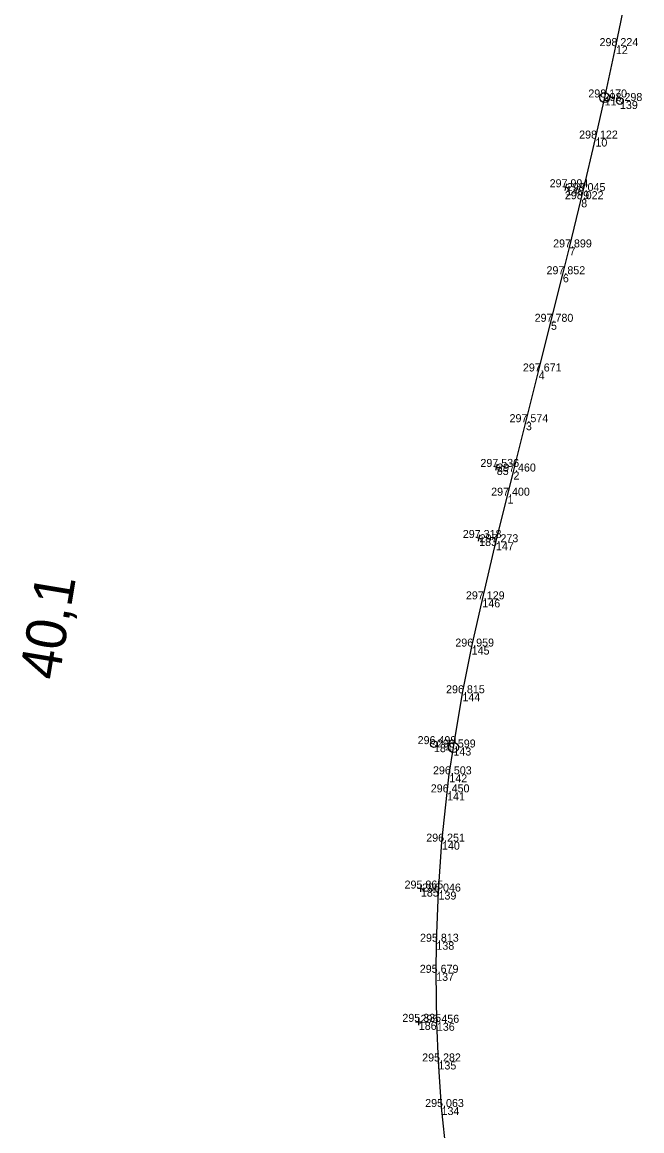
# Model space of a CAD drawing. Extents: x -684938 to -684389, y -1007777 to -1006471.
# Drawn here: x -684578.3 to -684485.4, y -1007291.1 to -1007124.9 of the extents above; entities that cross this region are included whole.
import ezdxf

# ---------------------------------------------------------------- set-up
doc = ezdxf.new("R2010")
doc.units = 0
for name, color, linetype in [('Vrstva 1', 7, 'Continuous'), ('Vrstva 60', 7, 'Continuous'), ('Vrstva 61', 7, 'Continuous'), ('Vrstva 7', 7, 'Continuous')]:
    doc.layers.add(name, color=color, linetype=linetype)

msp = doc.modelspace()

# ---------------------------------------------------------------- linework, layer by layer
at = {"layer": 'Vrstva 1'}
msp.add_lwpolyline([(-684514.7, -1007294.72), (-684515.43, -1007287.58), (-684515.89, -1007280.75), (-684516.13, -1007274.95), (-684516.23, -1007267.46), (-684516.2, -1007262.8), (-684515.88, -1007255.28), (-684515.36, -1007247.8), (-684514.59, -1007240.41), (-684514.26, -1007237.7), (-684513.65, -1007233.68), (-684512.29, -1007225.55), (-684510.91, -1007218.55), (-684509.31, -1007211.47), (-684507.27, -1007202.91), (-684505.54, -1007195.93), (-684504.64, -1007192.31), (-684502.78, -1007184.91), (-684500.87, -1007177.31), (-684499.02, -1007169.86), (-684497.24, -1007162.73), (-684496.25, -1007158.71), (-684494.49, -1007151.48), (-684494.2, -1007150.27), (-684492.36, -1007142.39), (-684490.97, -1007136.23), (-684489.29, -1007128.53), (-684487.68, -1007120.78)], dxfattribs=at)
at = {"layer": 'Vrstva 60'}
for p, q in [((-684489.29, -1007128.53), (-684489.29, -1007128.53)), ((-684490.97, -1007136.23), (-684490.97, -1007136.23)), ((-684488.68, -1007136.76), (-684488.68, -1007136.76)), ((-684492.36, -1007142.39), (-684492.36, -1007142.39)), ((-684496.77, -1007149.69), (-684496.77, -1007149.69)), ((-684494.2, -1007150.27), (-684494.2, -1007150.27)), ((-684494.49, -1007151.48), (-684494.49, -1007151.48)), ((-684496.25, -1007158.71), (-684496.25, -1007158.71)), ((-684497.24, -1007162.73), (-684497.24, -1007162.73)), ((-684499.02, -1007169.86), (-684499.02, -1007169.86)), ((-684500.87, -1007177.31), (-684500.87, -1007177.31)), ((-684502.78, -1007184.91), (-684502.78, -1007184.91)), ((-684507.15, -1007191.62), (-684507.15, -1007191.62)), ((-684504.64, -1007192.31), (-684504.64, -1007192.31)), ((-684505.54, -1007195.93), (-684505.54, -1007195.93)), ((-684509.79, -1007202.27), (-684509.79, -1007202.27)), ((-684507.27, -1007202.91), (-684507.27, -1007202.91)), ((-684509.31, -1007211.47), (-684509.31, -1007211.47)), ((-684510.91, -1007218.55), (-684510.91, -1007218.55)), ((-684512.29, -1007225.55), (-684512.29, -1007225.55)), ((-684516.56, -1007233.18), (-684516.56, -1007233.18)), ((-684513.65, -1007233.68), (-684513.65, -1007233.68)), ((-684514.26, -1007237.7), (-684514.26, -1007237.7)), ((-684514.59, -1007240.41), (-684514.59, -1007240.41)), ((-684515.36, -1007247.8), (-684515.36, -1007247.8)), ((-684518.52, -1007254.83), (-684518.52, -1007254.83)), ((-684515.88, -1007255.28), (-684515.88, -1007255.28)), ((-684516.2, -1007262.8), (-684516.2, -1007262.8)), ((-684516.23, -1007267.46), (-684516.23, -1007267.46)), ((-684518.84, -1007274.81), (-684518.84, -1007274.81)), ((-684516.13, -1007274.95), (-684516.13, -1007274.95)), ((-684515.89, -1007280.75), (-684515.89, -1007280.75)), ((-684515.43, -1007287.58), (-684515.43, -1007287.58))]:
    msp.add_line(p, q, dxfattribs=at)
at = {"layer": 'Vrstva 7'}
for p, q in [((-684488.69, -1007136.81), (-684488.67, -1007136.71)), ((-684496.88, -1007150.18), (-684496.65, -1007149.2)), ((-684497.25, -1007149.57), (-684496.28, -1007149.8)), ((-684507.64, -1007191.5), (-684506.67, -1007191.75)), ((-684507.27, -1007192.11), (-684507.03, -1007191.14)), ((-684510.27, -1007202.15), (-684509.3, -1007202.39)), ((-684509.91, -1007202.75), (-684509.67, -1007201.78)), ((-684516.56, -1007233.23), (-684516.55, -1007233.13)), ((-684519.02, -1007254.79), (-684518.02, -1007254.86)), ((-684518.55, -1007255.32), (-684518.48, -1007254.33)), ((-684519.34, -1007274.82), (-684518.34, -1007274.81)), ((-684518.83, -1007275.31), (-684518.85, -1007274.31))]:
    msp.add_line(p, q, dxfattribs=at)
for centre, radius in [((-684490.97, -1007136.24), 0.75), ((-684488.68, -1007136.76), 0.5), ((-684516.56, -1007233.18), 0.5), ((-684513.65, -1007233.67), 0.75)]:
    msp.add_circle(centre, radius, dxfattribs=at)

# ---------------------------------------------------------------- texts
at = {"layer": 'Vrstva 60'}
for s, p in [('12', (-684489.29, -1007129.72)), ('11', (-684490.97, -1007137.43)), ('139', (-684488.68, -1007137.96)), ('10', (-684492.36, -1007143.59)), ('140', (-684496.77, -1007150.89)), ('9', (-684494.2, -1007151.47)), ('8', (-684494.49, -1007152.69)), ('7', (-684496.25, -1007159.91)), ('6', (-684497.24, -1007163.93)), ('5', (-684499.02, -1007171.06)), ('4', (-684500.87, -1007178.51)), ('3', (-684502.78, -1007186.11)), ('85', (-684507.15, -1007192.82)), ('2', (-684504.64, -1007193.51)), ('1', (-684505.54, -1007197.13)), ('183', (-684509.79, -1007203.47)), ('147', (-684507.27, -1007204.11)), ('146', (-684509.31, -1007212.67)), ('145', (-684510.91, -1007219.75)), ('144', (-684512.29, -1007226.75)), ('184', (-684516.56, -1007234.38)), ('143', (-684513.65, -1007234.88)), ('142', (-684514.26, -1007238.9)), ('141', (-684514.59, -1007241.61)), ('140', (-684515.36, -1007249)), ('185', (-684518.52, -1007256.03)), ('139', (-684515.88, -1007256.48)), ('138', (-684516.2, -1007264)), ('137', (-684516.23, -1007268.66)), ('186', (-684518.84, -1007276.01)), ('136', (-684516.13, -1007276.15)), ('135', (-684515.89, -1007281.95)), ('134', (-684515.43, -1007288.78))]:
    msp.add_text(s, height=1.2, dxfattribs=at).set_placement(p)
at = {"layer": 'Vrstva 61'}
for s, p in [('298.224', (-684491.74, -1007128.53)), ('298.170', (-684493.42, -1007136.23)), ('298.298', (-684491.13, -1007136.76)), ('298.122', (-684494.8, -1007142.39)), ('297.994', (-684499.22, -1007149.69)), ('298.045', (-684496.66, -1007150.27)), ('298.022', (-684496.94, -1007151.48)), ('297.899', (-684498.7, -1007158.71)), ('297.852', (-684499.69, -1007162.73)), ('297.780', (-684501.47, -1007169.86)), ('297.671', (-684503.23, -1007177.31)), ('297.574', (-684505.23, -1007184.91)), ('297.536', (-684509.6, -1007191.62)), ('297.460', (-684507.09, -1007192.31)), ('297.400', (-684507.99, -1007195.93)), ('297.318', (-684512.24, -1007202.27)), ('297.273', (-684509.72, -1007202.91)), ('297.129', (-684511.77, -1007211.47)), ('296.959', (-684513.36, -1007218.55)), ('296.815', (-684514.75, -1007225.55)), ('296.499', (-684519.01, -1007233.18)), ('296.599', (-684516.11, -1007233.68)), ('296.503', (-684516.71, -1007237.7)), ('296.450', (-684517.04, -1007240.41)), ('296.251', (-684517.72, -1007247.8)), ('295.865', (-684520.97, -1007254.83)), ('296.046', (-684518.33, -1007255.28)), ('295.813', (-684518.65, -1007262.8)), ('295.679', (-684518.69, -1007267.46)), ('295.335', (-684521.3, -1007274.81)), ('295.456', (-684518.58, -1007274.95)), ('295.282', (-684518.33, -1007280.75)), ('295.063', (-684517.88, -1007287.58))]:
    msp.add_text(s, height=1.2, dxfattribs=at).set_placement(p)
at = {"layer": 'Vrstva 7'}
msp.add_text('40,1', height=6, rotation=80.4863, dxfattribs=at).set_placement((-684572.82, -1007223.75))

doc.saveas('drawing.dxf')
